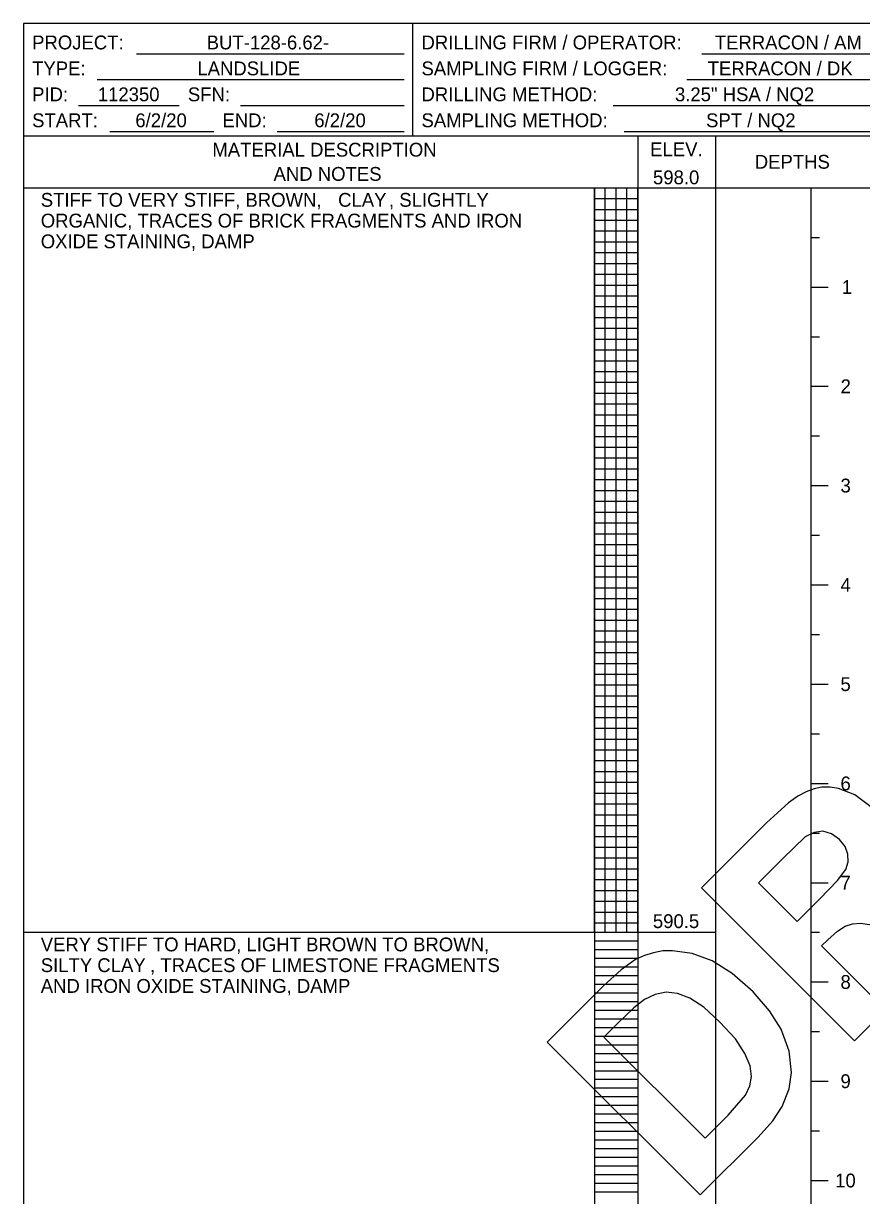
# Model space of a CAD drawing. Extents: x -0.01 to 0.83, y -0.48 to 1.27.
# Drawn here: x 0 to 0.404, y 0.71 to 1.275 of the extents above; entities that cross this region are included whole.
import ezdxf

# ---------------------------------------------------------------- set-up
doc = ezdxf.new("R2010")
doc.units = 0

# ---------------------------------------------------------------- blocks, each defined once
blk = doc.blocks.new('DGRFC!DRAFT - ARIAL')
for points in [[(0, 0), (0.03155, 0), (0.03997, 0.00043), (0.04651, 0.00179), (0.05315, 0.00468), (0.05825, 0.00842), (0.06344, 0.01497), (0.06726, 0.02313), (0.06913, 0.03129), (0.06981, 0.0409), (0.06913, 0.05162), (0.06709, 0.06054), (0.06369, 0.06794), (0.05901, 0.07406), (0.05638, 0.07662), (0.05332, 0.07874), (0.05008, 0.08044), (0.0466, 0.08172), (0.03988, 0.08291), (0.03078, 0.08333), (0, 0.08333)], [(0.0841, 0), (0.10094, 0), (0.10094, 0.03478), (0.10434, 0.03478), (0.10935, 0.03452), (0.11275, 0.03376), (0.11539, 0.0324), (0.11786, 0.03036), (0.1267, 0.01811), (0.13878, 0), (0.15893, 0), (0.14872, 0.01616), (0.14337, 0.02449), (0.1392, 0.02976), (0.1352, 0.03333), (0.13027, 0.03673), (0.13537, 0.03776), (0.1398, 0.03946), (0.14354, 0.04167), (0.14668, 0.04439), (0.14906, 0.0477), (0.15085, 0.05136), (0.15187, 0.05544), (0.15221, 0.05986), (0.15128, 0.06692), (0.14847, 0.07313), (0.1466, 0.07577), (0.1443, 0.07798), (0.14175, 0.07968), (0.13878, 0.08104), (0.13537, 0.08206), (0.13095, 0.08274), (0.11947, 0.08333), (0.0841, 0.08333)], [(0.15952, 0), (0.1773, 0), (0.18427, 0.01896), (0.21752, 0.01896), (0.22474, 0), (0.24311, 0), (0.20978, 0.08333), (0.19192, 0.08333)], [(0.25204, 0), (0.26888, 0), (0.26888, 0.03546), (0.30349, 0.03546), (0.30349, 0.04949), (0.26888, 0.04949), (0.26888, 0.06922), (0.30901, 0.06922), (0.30901, 0.08333), (0.25204, 0.08333)], [(0.34167, 0), (0.3585, 0), (0.3585, 0.06922), (0.38308, 0.06922), (0.38308, 0.08333), (0.31701, 0.08333), (0.31701, 0.06922), (0.34167, 0.06922)], [(0.01684, 0.01412), (0.02942, 0.01412), (0.03954, 0.01488), (0.04328, 0.01616), (0.04634, 0.01828), (0.04881, 0.02151), (0.05077, 0.02636), (0.05213, 0.03291), (0.05247, 0.04167), (0.05213, 0.05017), (0.05085, 0.05646), (0.04872, 0.06105), (0.046, 0.06446), (0.04243, 0.06692), (0.03818, 0.06845), (0.03299, 0.06905), (0.0244, 0.06922), (0.01684, 0.06922)], [(0.10094, 0.04804), (0.11335, 0.04804), (0.12313, 0.0483), (0.1284, 0.04906), (0.13112, 0.05051), (0.13308, 0.05264), (0.13444, 0.05544), (0.13486, 0.05884), (0.13427, 0.06267), (0.13257, 0.06565), (0.12985, 0.06777), (0.12628, 0.06896), (0.11403, 0.06922), (0.10094, 0.06922)], [(0.18937, 0.03299), (0.21216, 0.03299), (0.20068, 0.06386)]]:
    blk.add_lwpolyline(points, close=True)

msp = doc.modelspace()

# ---------------------------------------------------------------- linework, layer by layer
msp.add_lwpolyline([(0, 0), (0.83333, 0), (0.83333, 1.275), (0, 1.275)], close=True)
msp.add_lwpolyline([(0, 0), (0.83333, 0), (0.83333, 1.275), (0, 1.275)], close=True)
msp.add_lwpolyline([(0, 0), (0.83333, 0), (0.83333, 1.275), (0, 1.275)], close=True)
msp.add_lwpolyline([(0, 0), (0.83333, 0), (0.83333, 1.275), (0, 1.275)], close=True)
msp.add_lwpolyline([(0, 0), (0.83333, 0), (0.83333, 1.275), (0, 1.275)], close=True)
for points in [[(0.1875, 1.22083), (0.1875, 1.275)], [(0.05444, 1.26041), (0.18333, 1.26041)], [(0.32667, 1.26041), (0.4125, 1.26041)], [(0.03542, 1.24791), (0.18333, 1.24791)], [(0.31944, 1.24791), (0.4125, 1.24791)], [(0.02653, 1.23541), (0.075, 1.23541)], [(0.10458, 1.23541), (0.18333, 1.23541)], [(0.28403, 1.23541), (0.4125, 1.23541)], [(0, 1.22083), (0.83333, 1.22083)], [(0, 1.22083), (0.83333, 1.22083)], [(0, 1.22083), (0.83333, 1.22083)], [(0, 1.22083), (0.83333, 1.22083)], [(0, 1.22083), (0.83333, 1.22083)], [(0.04153, 1.22291), (0.09167, 1.22291)], [(0.12222, 1.22291), (0.18333, 1.22291)], [(0.2893, 1.22291), (0.4125, 1.22291)], [(0.29583, 1.22083), (0.29583, -0.47833)], [(0.29583, 1.22083), (0.29583, -0.47833)], [(0.33333, 1.22083), (0.33333, -0.47833)], [(0.33333, 1.22083), (0.33333, -0.47833)], [(0, 1.19583), (0.83333, 1.19583)], [(0, 1.19583), (0.83333, 1.19583)], [(0, 1.19583), (0.83333, 1.19583)], [(0, 1.19583), (0.83333, 1.19583)], [(0, 1.19583), (0.83333, 1.19583)], [(0.275, 1.19583), (0.29583, 1.19583)], [(0.275, 0.83708), (0.275, 1.19583)], [(0.275, 1.19583), (0.275, 0.83708)], [(0.275, 1.19583), (0.275, -0.47833)], [(0.28021, 0.83708), (0.28021, 1.19583)], [(0.28542, 0.83708), (0.28542, 1.19583)], [(0.29062, 0.83708), (0.29062, 1.19583)], [(0.29583, 0.83708), (0.29583, 1.19583)], [(0.29583, 1.19583), (0.33333, 1.19583)], [(0.37917, 1.19583), (0.37917, -0.47833)], [(0.275, 1.19062), (0.29583, 1.19062)], [(0.275, 1.18541), (0.29583, 1.18541)], [(0.275, 1.18021), (0.29583, 1.18021)], [(0.275, 1.175), (0.29583, 1.175)], [(0.275, 1.16979), (0.29583, 1.16979)], [(0.37917, 1.17191), (0.38333, 1.17191)], [(0.275, 1.16458), (0.29583, 1.16458)], [(0.275, 1.15937), (0.29583, 1.15937)], [(0.275, 1.15416), (0.29583, 1.15416)], [(0.275, 1.14896), (0.29583, 1.14896)], [(0.37917, 1.148), (0.3875, 1.148)], [(0.37917, 1.148), (0.38333, 1.148)], [(0.275, 1.14375), (0.29583, 1.14375)], [(0.275, 1.13854), (0.29583, 1.13854)], [(0.275, 1.13333), (0.29583, 1.13333)], [(0.275, 1.12812), (0.29583, 1.12812)], [(0.37917, 1.12408), (0.38333, 1.12408)], [(0.275, 1.12291), (0.29583, 1.12291)], [(0.275, 1.11771), (0.29583, 1.11771)], [(0.275, 1.1125), (0.29583, 1.1125)], [(0.275, 1.10729), (0.29583, 1.10729)], [(0.275, 1.10208), (0.29583, 1.10208)], [(0.275, 1.09687), (0.29583, 1.09687)], [(0.37917, 1.10016), (0.3875, 1.10016)], [(0.37917, 1.10016), (0.38333, 1.10016)], [(0.275, 1.09166), (0.29583, 1.09166)], [(0.275, 1.08646), (0.29583, 1.08646)], [(0.275, 1.08125), (0.29583, 1.08125)], [(0.275, 1.07604), (0.29583, 1.07604)], [(0.37917, 1.07625), (0.38333, 1.07625)], [(0.275, 1.07083), (0.29583, 1.07083)], [(0.275, 1.06562), (0.29583, 1.06562)], [(0.275, 1.06041), (0.29583, 1.06041)], [(0.275, 1.05521), (0.29583, 1.05521)], [(0.37917, 1.05233), (0.3875, 1.05233)], [(0.37917, 1.05233), (0.38333, 1.05233)], [(0.275, 1.05), (0.29583, 1.05)], [(0.275, 1.04479), (0.29583, 1.04479)], [(0.275, 1.03958), (0.29583, 1.03958)], [(0.275, 1.03437), (0.29583, 1.03437)], [(0.275, 1.02916), (0.29583, 1.02916)], [(0.37917, 1.02841), (0.38333, 1.02841)], [(0.275, 1.02396), (0.29583, 1.02396)], [(0.275, 1.01875), (0.29583, 1.01875)], [(0.275, 1.01354), (0.29583, 1.01354)], [(0.275, 1.00833), (0.29583, 1.00833)], [(0.275, 1.00312), (0.29583, 1.00312)], [(0.37917, 1.0045), (0.3875, 1.0045)], [(0.37917, 1.0045), (0.38333, 1.0045)], [(0.275, 0.99791), (0.29583, 0.99791)], [(0.275, 0.99271), (0.29583, 0.99271)], [(0.275, 0.9875), (0.29583, 0.9875)], [(0.275, 0.98229), (0.29583, 0.98229)], [(0.275, 0.97708), (0.29583, 0.97708)], [(0.37917, 0.98058), (0.38333, 0.98058)], [(0.275, 0.97187), (0.29583, 0.97187)], [(0.275, 0.96666), (0.29583, 0.96666)], [(0.275, 0.96146), (0.29583, 0.96146)], [(0.275, 0.95625), (0.29583, 0.95625)], [(0.37917, 0.95666), (0.3875, 0.95666)], [(0.37917, 0.95666), (0.38333, 0.95666)], [(0.275, 0.95104), (0.29583, 0.95104)], [(0.275, 0.94583), (0.29583, 0.94583)], [(0.275, 0.94062), (0.29583, 0.94062)], [(0.275, 0.93541), (0.29583, 0.93541)], [(0.37917, 0.93275), (0.38333, 0.93275)], [(0.275, 0.93021), (0.29583, 0.93021)], [(0.275, 0.925), (0.29583, 0.925)], [(0.275, 0.91979), (0.29583, 0.91979)], [(0.275, 0.91458), (0.29583, 0.91458)], [(0.275, 0.90937), (0.29583, 0.90937)], [(0.275, 0.90416), (0.29583, 0.90416)], [(0.37917, 0.90883), (0.3875, 0.90883)], [(0.37917, 0.90883), (0.38333, 0.90883)], [(0.275, 0.89896), (0.29583, 0.89896)], [(0.275, 0.89375), (0.29583, 0.89375)], [(0.275, 0.88854), (0.29583, 0.88854)], [(0.275, 0.88333), (0.29583, 0.88333)], [(0.37917, 0.88491), (0.38333, 0.88491)], [(0.275, 0.87812), (0.29583, 0.87812)], [(0.275, 0.87291), (0.29583, 0.87291)], [(0.275, 0.86771), (0.29583, 0.86771)], [(0.275, 0.8625), (0.29583, 0.8625)], [(0.37917, 0.861), (0.3875, 0.861)], [(0.37917, 0.861), (0.38333, 0.861)], [(0.275, 0.85729), (0.29583, 0.85729)], [(0.275, 0.85208), (0.29583, 0.85208)], [(0.275, 0.84687), (0.29583, 0.84687)], [(0.275, 0.84166), (0.29583, 0.84166)], [(0, 0.83708), (0.275, 0.83708)], [(0.275, 0.83708), (0.29583, 0.83708)], [(0.275, 0.83708), (0.29583, 0.83708)], [(0.275, 0.83708), (0.275, 0.23917)], [(0.29583, 0.83708), (0.33333, 0.83708)], [(0.37917, 0.83708), (0.38333, 0.83708)], [(0.275, 0.83292), (0.29583, 0.83292)], [(0.275, 0.82875), (0.29583, 0.82875)], [(0.275, 0.82458), (0.29583, 0.82458)], [(0.275, 0.82042), (0.29583, 0.82042)], [(0.275, 0.81625), (0.29583, 0.81625)], [(0.275, 0.81208), (0.29583, 0.81208)], [(0.275, 0.80792), (0.29583, 0.80792)], [(0.37917, 0.81317), (0.3875, 0.81317)], [(0.37917, 0.81317), (0.38333, 0.81317)], [(0.275, 0.80375), (0.29583, 0.80375)], [(0.275, 0.79958), (0.29583, 0.79958)], [(0.275, 0.79542), (0.29583, 0.79542)], [(0.275, 0.79125), (0.29583, 0.79125)], [(0.275, 0.78708), (0.29583, 0.78708)], [(0.37917, 0.78925), (0.38333, 0.78925)], [(0.275, 0.78292), (0.29583, 0.78292)], [(0.275, 0.77875), (0.29583, 0.77875)], [(0.275, 0.77458), (0.29583, 0.77458)], [(0.275, 0.77042), (0.29583, 0.77042)], [(0.275, 0.76625), (0.29583, 0.76625)], [(0.37917, 0.76533), (0.3875, 0.76533)], [(0.37917, 0.76533), (0.38333, 0.76533)], [(0.275, 0.76208), (0.29583, 0.76208)], [(0.275, 0.75792), (0.29583, 0.75792)], [(0.275, 0.75375), (0.29583, 0.75375)], [(0.275, 0.74958), (0.29583, 0.74958)], [(0.275, 0.74542), (0.29583, 0.74542)], [(0.275, 0.74125), (0.29583, 0.74125)], [(0.37917, 0.74142), (0.38333, 0.74142)], [(0.275, 0.73708), (0.29583, 0.73708)], [(0.275, 0.73292), (0.29583, 0.73292)], [(0.275, 0.72875), (0.29583, 0.72875)], [(0.275, 0.72458), (0.29583, 0.72458)], [(0.275, 0.72042), (0.29583, 0.72042)], [(0.37917, 0.7175), (0.3875, 0.7175)], [(0.37917, 0.7175), (0.38333, 0.7175)], [(0.275, 0.71625), (0.29583, 0.71625)], [(0.275, 0.71208), (0.29583, 0.71208)]]:
    msp.add_lwpolyline(points)

# ---------------------------------------------------------------- block references
at = {"xscale": 1.25, "yscale": 1.25, "rotation": 45}
msp.add_blockref('DGRFC!DRAFT - ARIAL', (0.32586, 0.71054), dxfattribs=at)

# ---------------------------------------------------------------- texts
for s, height, p in [('PROJECT:', 0.006667, (0.00417, 1.2625)), ('BUT-128-6.62-', 0.0066667, (0.08824, 1.2625)), ('DRILLING FIRM / OPERATOR:', 0.0066667, (0.19167, 1.2625)), ('TERRACON / AM', 0.0066667, (0.33293, 1.2625)), ('TYPE:', 0.006667, (0.00417, 1.25)), ('LANDSLIDE', 0.006667, (0.08374, 1.25)), ('SAMPLING FIRM / LOGGER:', 0.0066667, (0.19167, 1.25)), ('TERRACON / DK', 0.0066667, (0.32949, 1.25)), ('PID:', 0.006667, (0.00417, 1.2375)), ('112350', 0.006667, (0.0358, 1.2375)), ('SFN:', 0.006667, (0.07917, 1.2375)), ('DRILLING METHOD:', 0.0066667, (0.19167, 1.2375)), ('3.25" HSA / NQ2', 0.0066667, (0.31373, 1.2375)), ('START:', 0.006667, (0.00417, 1.225)), ('6/2/20', 0.006667, (0.05388, 1.225)), ('END:', 0.006667, (0.09583, 1.225)), ('6/2/20', 0.006667, (0.14006, 1.225)), ('SAMPLING METHOD:', 0.0066667, (0.19167, 1.225)), ('SPT / NQ2', 0.006667, (0.32872, 1.225)), ('MATERIAL DESCRIPTION', 0.0066667, (0.09097, 1.21083)), ('ELEV.', 0.006667, (0.30179, 1.21104)), ('DEPTHS', 0.006667, (0.35218, 1.205)), ('AND NOTES', 0.006667, (0.12044, 1.19916)), ('598.0', 0.006667, (0.30316, 1.1975)), ('STIFF TO VERY STIFF, BROWN, ', 0.0066667, (0.00833, 1.18666)), ('CLAY', 0.006667, (0.15153, 1.18666)), (', SLIGHTLY', 0.006667, (0.17604, 1.18666)), ('ORGANIC, TRACES OF BRICK FRAGMENTS AND IRON', 0.0066667, (0.00833, 1.17666)), ('OXIDE STAINING, DAMP', 0.0066667, (0.00833, 1.16666)), ('1', 0.00667, (0.3941, 1.14466)), ('2', 0.00667, (0.39349, 1.09683)), ('3', 0.00667, (0.39345, 1.049)), ('4', 0.00667, (0.39347, 1.00116)), ('5', 0.00667, (0.39343, 0.95333)), ('6', 0.00667, (0.39345, 0.9055)), ('7', 0.00667, (0.39345, 0.85766)), ('590.5', 0.006667, (0.30312, 0.83913)), ('VERY STIFF TO HARD, LIGHT BROWN TO BROWN,', 0.0066667, (0.00833, 0.82792)), ('SILTY CLAY', 0.006667, (0.00833, 0.81792)), (', TRACES OF LIMESTONE FRAGMENTS', 0.0066667, (0.06097, 0.81792)), ('AND IRON OXIDE STAINING, DAMP', 0.0066667, (0.00833, 0.80792)), ('8', 0.00667, (0.39345, 0.80983)), ('9', 0.00667, (0.39345, 0.762)), ('10', 0.006667, (0.39088, 0.71417))]:
    msp.add_text(s, height=height).set_placement(p)

doc.saveas('drawing.dxf')
